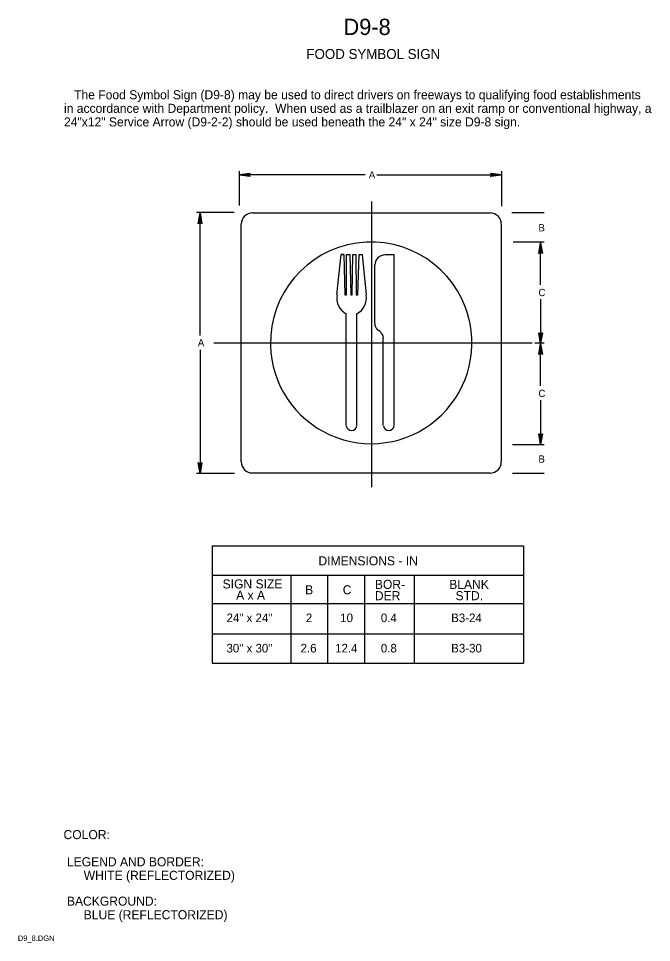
# Model space of a CAD drawing. Extents: x 0.013 to 0.188, y 0.004 to 0.259.
import ezdxf

# ---------------------------------------------------------------- set-up
doc = ezdxf.new("R2010")
doc.units = 0
for name, color, linetype in [('1', 7, 'Continuous'), ('2', 7, 'Continuous'), ('3', 7, 'Continuous')]:
    doc.layers.add(name, color=color, linetype=linetype)

# ---------------------------------------------------------------- blocks, each defined once
blk = doc.blocks.new('RARROW')
at = {"layer": '3'}
for p, q in [((-2.156, 0.28500000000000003), (-2.2665, 0.384625)), ((-2.2665, 0.384625), (0, 0)), ((0, 0), (-2.2665, -0.379125)), ((-2.156, 0.28500000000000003), (-2.075625, 0.12075)), ((0, 0), (-2.156, 0.28500000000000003)), ((-2.14975, -0.2705), (0, 0)), ((-2.075625, 0.12075), (0, 0)), ((0, 0), (-2.074, -0.108)), ((-2.2665, -0.379125), (-2.14975, -0.2705)), ((-2.074, -0.108), (-2.14975, -0.2705))]:
    blk.add_line(p, q, dxfattribs=at)

msp = doc.modelspace()

# ---------------------------------------------------------------- linework, layer by layer
at = {"layer": '1'}
msp.add_line((0.11025, 0.208625), (0.11025, 0.12975), dxfattribs=at)
at = {"layer": '2'}
msp.add_line((0.066625, 0.169625), (0.154625, 0.169625), dxfattribs=at)
at = {"layer": '3'}
for p, q in [((0.07377757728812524, 0.20753155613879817), (0.07377757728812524, 0.21703155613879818)), ((0.1462424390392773, 0.207375), (0.1462424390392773, 0.217)), ((0.1085, 0.216), (0.07387232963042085, 0.216)), ((0.11175, 0.216), (0.1462424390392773, 0.216)), ((0.07225, 0.20555422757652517), (0.061875, 0.20555422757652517)), ((0.062875, 0.171625), (0.062875, 0.20555422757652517)), ((0.077375, 0.20550000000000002), (0.14300000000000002, 0.20550000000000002)), ((0.149, 0.205625), (0.158, 0.205625)), ((0.07425, 0.13675), (0.07425, 0.202375)), ((0.146125, 0.202375), (0.146125, 0.13675)), ((0.149375, 0.1975), (0.158, 0.1975)), ((0.157, 0.1935), (0.157, 0.1975)), ((0.157, 0.185625), (0.157, 0.1975)), ((0.100625, 0.182875), (0.10187500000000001, 0.194)), ((0.10262500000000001, 0.194), (0.10187500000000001, 0.194)), ((0.10187500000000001, 0.194), (0.10262500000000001, 0.194)), ((0.10262500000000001, 0.194), (0.10187500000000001, 0.194)), ((0.10187500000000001, 0.194), (0.10262500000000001, 0.194)), ((0.10187500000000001, 0.194), (0.10262500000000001, 0.194)), ((0.10262500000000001, 0.194), (0.10287500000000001, 0.182875)), ((0.10337500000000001, 0.194), (0.10425, 0.194)), ((0.10337500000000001, 0.182875), (0.10337500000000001, 0.194)), ((0.10337500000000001, 0.194), (0.10425, 0.194)), ((0.10425, 0.194), (0.1045, 0.182875)), ((0.10425, 0.194), (0.1045, 0.182875)), ((0.104875, 0.182875), (0.105125, 0.194)), ((0.104875, 0.182875), (0.105125, 0.194)), ((0.105125, 0.194), (0.105875, 0.194)), ((0.105125, 0.194), (0.105875, 0.194)), ((0.105875, 0.194), (0.106, 0.182875)), ((0.1065, 0.182875), (0.106875, 0.194)), ((0.106875, 0.194), (0.107625, 0.194)), ((0.107625, 0.194), (0.10875, 0.182875)), ((0.114, 0.194), (0.116375, 0.194)), ((0.115625, 0.194), (0.11625, 0.194)), ((0.116375, 0.194), (0.116375, 0.14675)), ((0.111125, 0.17500000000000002), (0.111125, 0.19112500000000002)), ((0.10287500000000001, 0.182875), (0.10337500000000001, 0.182875)), ((0.1045, 0.182875), (0.104875, 0.182875)), ((0.106, 0.182875), (0.1065, 0.182875)), ((0.157, 0.181625), (0.157, 0.169625)), ((0.10325000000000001, 0.14675), (0.10325000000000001, 0.177625)), ((0.106125, 0.177625), (0.106125, 0.14675)), ((0.137, 0.17675), (0.137, 0.177)), ((0.112625, 0.17275000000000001), (0.11175, 0.17325000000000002)), ((0.1135, 0.14675), (0.1135, 0.170875)), ((0.155375, 0.169625), (0.158, 0.169625)), ((0.157, 0.15775), (0.157, 0.169625)), ((0.062875, 0.167625), (0.062875, 0.13354871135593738)), ((0.109875, 0.167375), (0.109875, 0.167375)), ((0.157, 0.15375), (0.157, 0.14175000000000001)), ((0.157, 0.14575), (0.157, 0.14175000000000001)), ((0.14925, 0.14150000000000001), (0.158, 0.14150000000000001)), ((0.072375, 0.13350397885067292), (0.061875, 0.13350397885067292)), ((0.14300000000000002, 0.133625), (0.077375, 0.133625)), ((0.14925, 0.133625), (0.158, 0.133625)), ((0.06621145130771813, 0.11358842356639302), (0.06621145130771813, 0.08111248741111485)), ((0.06621145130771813, 0.11348748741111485), (0.15221145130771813, 0.11348748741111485)), ((0.15221145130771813, 0.11348748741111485), (0.15221145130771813, 0.08111248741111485)), ((0.15221145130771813, 0.10536248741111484), (0.06621145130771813, 0.10536248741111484)), ((0.08796145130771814, 0.10536248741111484), (0.08796145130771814, 0.08111248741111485)), ((0.09807933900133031, 0.10536248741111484), (0.09807933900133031, 0.08111248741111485)), ((0.10832933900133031, 0.10536248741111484), (0.10832933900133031, 0.08111248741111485)), ((0.12200982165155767, 0.10533842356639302), (0.12200982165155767, 0.08111248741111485)), ((0.06621145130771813, 0.09761248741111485), (0.15221145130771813, 0.09761248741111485)), ((0.06621145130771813, 0.08923748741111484), (0.15221145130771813, 0.08923748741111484)), ((0.06621145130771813, 0.08111248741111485), (0.15221145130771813, 0.08111248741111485))]:
    msp.add_line(p, q, dxfattribs=at)
for centre, radius, start, end in [((0.07737499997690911, 0.2023750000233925), 0.003124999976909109, 90, 180), ((0.1430000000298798, 0.20237500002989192), 0.003124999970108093, 0, 90), ((0.11015095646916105, 0.16958214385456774), 0.02784375, 15.255119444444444, 181.20605), ((0.11401155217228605, 0.19103844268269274), 0.00284765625, 90, 180), ((0.10557799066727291, 0.1819425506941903), 0.004924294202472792, 169.96161666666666, 241.9229722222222), ((0.10389579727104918, 0.1819425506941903), 0.004924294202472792, 298.0770277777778, 10.038383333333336), ((0.11015095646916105, 0.16958214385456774), 0.02784375, 181.2710277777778, 15.01845000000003), ((0.11338533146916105, 0.17494358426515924), 0.0022500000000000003, 180, 228.0127888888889), ((0.11127595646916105, 0.17084776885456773), 0.0022500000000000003, 0, 53.13010277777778), ((0.10473689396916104, 0.14688683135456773), 0.001493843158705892, 188.72338055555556, 351.27661944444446), ((0.11500251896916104, 0.14688683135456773), 0.001493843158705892, 188.72338055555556, 351.27661944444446), ((0.07735471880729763, 0.13674936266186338), 0.0031047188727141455, 179.98823888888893, 269.98823888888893), ((0.1429999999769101, 0.13675000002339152), 0.0031250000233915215, 270, 0)]:
    msp.add_arc(centre, radius, start, end, dxfattribs=at)

# ---------------------------------------------------------------- block references
at = {"layer": '3', "xscale": 0.0013236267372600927, "yscale": 0.001309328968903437}
for p, rotation in [((0.07375, 0.216), 180), ((0.062875, 0.20550000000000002), 90), ((0.157, 0.19725), 90), ((0.157, 0.19725), 90), ((0.157, 0.169375), -90), ((0.157, 0.169375), 90), ((0.157, 0.14150000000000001), -90), ((0.157, 0.14150000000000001), -90), ((0.062875, 0.1335), -90)]:
    msp.add_blockref('RARROW', p, dxfattribs=dict(at, rotation=rotation))
msp.add_blockref('RARROW', (0.146125, 0.216), dxfattribs=at)

# ---------------------------------------------------------------- texts
at = {"layer": '1'}
for s, height, p in [('D9-8', 0.0045000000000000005, (0.10250000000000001, 0.254625)), ('FOOD SYMBOL SIGN', 0.00275025, (0.09225, 0.248)), ('COLOR:', 0.0024997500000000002, (0.025125, 0.0325)), (' LEGEND AND BORDER:', 0.0024997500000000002, (0.025125, 0.025)), ('      WHITE (REFLECTORIZED)', 0.0024997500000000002, (0.025125, 0.02125)), (' BACKGROUND:', 0.0024997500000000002, (0.025125, 0.014125)), ('      BLUE (REFLECTORIZED)', 0.0024997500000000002, (0.025125, 0.010375)), ('D9_8.DGN', 0.0015, (0.0125, 0.004375))]:
    msp.add_text(s, height=height, dxfattribs=at).set_placement(p)
at = {"layer": '2'}
for s, p in [('   The Food Symbol Sign (D9-8) may be used to direct drivers on freeways to qualifying food establishments', (0.02525, 0.23687525)), ('in accordance with Department policy.  When used as a trailblazer on an exit ramp or conventional highway, a', (0.02525, 0.23312549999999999)), ('24"x12" Service Arrow (D9-2-2) should be used beneath the 24" x 24" size D9-8 sign.', (0.02525, 0.22937575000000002))]:
    msp.add_text(s, height=0.0024997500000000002, dxfattribs=at).set_placement(p)
at = {"layer": '3'}
for s, height, p in [('A', 0.00200025, (0.1095, 0.215)), ('B', 0.00200025, (0.15637500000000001, 0.200375)), ('C', 0.00200025, (0.15637500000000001, 0.1825)), ('A', 0.00200025, (0.06225, 0.168625)), ('C', 0.00200025, (0.15637500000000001, 0.154625)), ('B', 0.00200025, (0.15637500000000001, 0.1365)), ('DIMENSIONS - IN', 0.0024997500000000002, (0.09557455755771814, 0.108125)), ('SIGN SIZE', 0.0024997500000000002, (0.06908680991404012, 0.10175000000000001)), ('B', 0.0024997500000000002, (0.09189918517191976, 0.100125)), ('C', 0.0024997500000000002, (0.10229837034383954, 0.100125)), ('BOR-', 0.0024997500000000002, (0.11117368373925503, 0.10162500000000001)), ('BLANK', 0.0024997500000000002, (0.13172450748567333, 0.10162500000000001)), ('A x A', 0.0024997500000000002, (0.07283680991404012, 0.098625)), ('DER', 0.0024997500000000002, (0.11117368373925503, 0.0985)), ('STD.', 0.0024997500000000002, (0.13347450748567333, 0.0985)), ('24" x 24"', 0.0023752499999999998, (0.07017081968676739, 0.092437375)), ('2', 0.0023752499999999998, (0.09209771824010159, 0.092437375)), ('10', 0.0023752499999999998, (0.10159562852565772, 0.092437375)), ('0.4', 0.0023752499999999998, (0.11283002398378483, 0.092437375)), ('B3-24', 0.0023752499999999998, (0.1322631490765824, 0.092437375)), ('30" x 30"', 0.0023752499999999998, (0.07017081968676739, 0.08406237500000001)), ('2.6', 0.0023752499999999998, (0.09064269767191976, 0.08406237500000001)), ('12.4', 0.0023752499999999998, (0.10018559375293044, 0.08406237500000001)), ('0.8', 0.0023752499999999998, (0.1128260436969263, 0.08406237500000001)), ('B3-30', 0.0023752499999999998, (0.1322696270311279, 0.08406237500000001))]:
    msp.add_text(s, height=height, dxfattribs=at).set_placement(p)

doc.saveas('drawing.dxf')
